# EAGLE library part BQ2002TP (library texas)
CHARGE MANAGEMENT IC
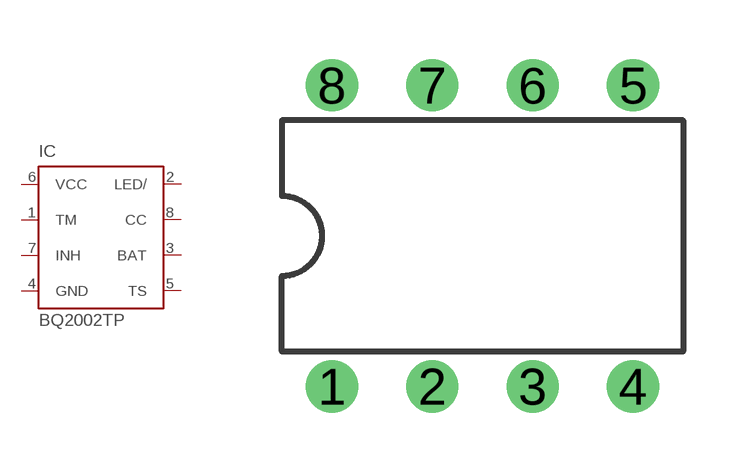
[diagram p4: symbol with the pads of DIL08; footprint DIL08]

Designator prefix IC

## BQ2002TP (MF: TEXAS INSTRUMENT CONNECTORS; MPN: BQ2002TPN; OC_FARNELL: 8409668; OC_NEWARK: 74C7526)  [DIL08]
1  TM  in
2  LED/  oc
3  BAT  in
4  GND  pwr
5  TS  in
6  VCC  pwr
7  INH  in
8  CC  oc

## Footprint DIL08 (pad centres in mm)
Dual In Line Package
drill 0.813 pad 1.27 round: 1 -3.81,-3.81; 2 -1.27,-3.81; 3 1.27,-3.81; 4 3.81,-3.81; 5 3.81,3.81; 6 1.27,3.81; 7 -1.27,3.81; 8 -3.81,3.81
